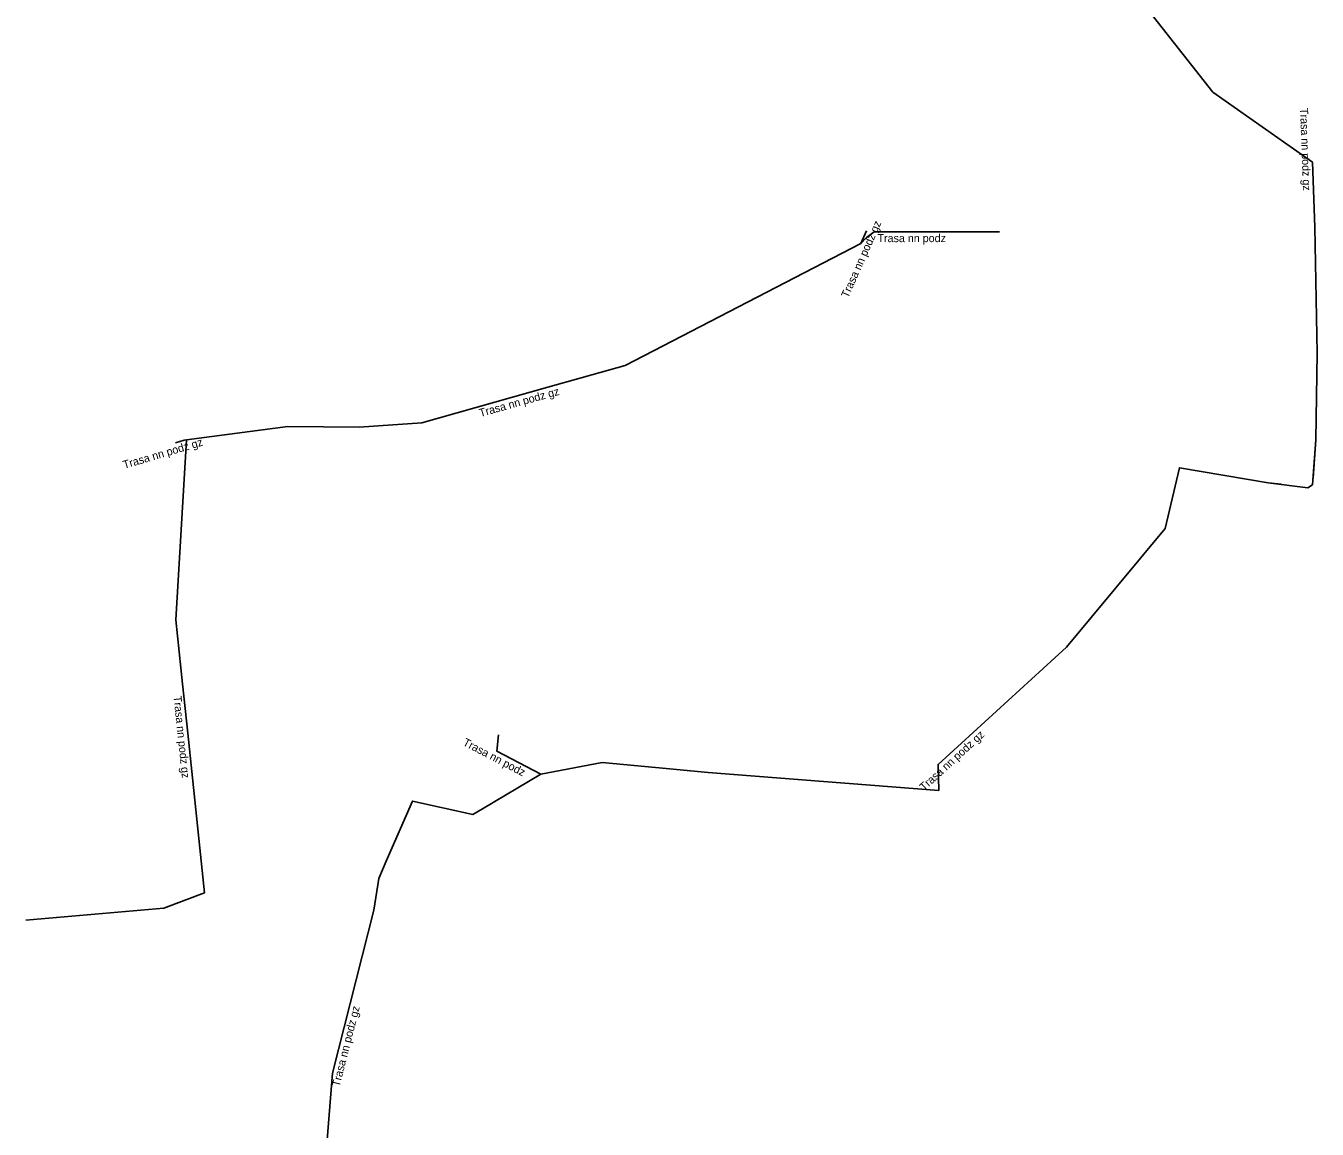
# Model space of a CAD drawing. Extents: x -778200 to -777730, y -1024936 to -1024518.
# Drawn here: x -778006.4 to -777925.8, y -1024799.4 to -1024730.5 of the extents above; entities that cross this region are included whole.
import ezdxf

# ---------------------------------------------------------------- set-up
doc = ezdxf.new("R2010")
doc.units = 0
for name, color, linetype in [('Popiskový text - Ostatní atributy Trasy', 7, 'Continuous'), ('Spojnice NN', 7, 'Continuous'), ('Spojnice VN', 7, 'Continuous')]:
    doc.layers.add(name, color=color, linetype=linetype)

msp = doc.modelspace()

# ---------------------------------------------------------------- linework, layer by layer
at = {"layer": 'Spojnice NN'}
for points in [[(-777926.024, -1024758.713), (-777925.859, -1024756.323), (-777925.772, -1024750.894), (-777925.919, -1024743.043), (-777926.069, -1024738.968), (-777927.663, -1024737.846), (-777932.279, -1024734.598), (-777936.001, -1024729.893), (-777939.603, -1024726.2)], [(-777954.263, -1024744.061), (-777953.915, -1024743.274)], [(-777954.263, -1024744.061), (-777953.928, -1024743.677), (-777953.432, -1024743.322), (-777946.135, -1024743.322), (-777945.617, -1024743.325)], [(-777996.382, -1024756.324), (-777990.058, -1024755.482), (-777985.6, -1024755.517), (-777981.696, -1024755.245), (-777973.822, -1024753.037), (-777968.999, -1024751.684), (-777954.263, -1024744.061)], [(-778006.425, -1024786.306), (-777997.797, -1024785.568), (-777995.266, -1024784.603), (-777996.309, -1024774.633), (-777996.632, -1024771.547), (-777997.051, -1024767.546), (-777996.382, -1024756.324)], [(-777997.067, -1024756.502), (-777996.534, -1024756.344), (-777996.382, -1024756.324)], [(-777974.257, -1024777.202), (-777970.422, -1024776.468), (-777967.09, -1024776.785), (-777963.818, -1024777.096), (-777949.411, -1024778.212), (-777949.445, -1024776.584), (-777945.079, -1024772.597), (-777941.428, -1024769.263), (-777935.268, -1024761.843), (-777934.375, -1024758.06), (-777928.824, -1024758.996), (-777928.014, -1024759.082)], [(-777976.907, -1024774.742), (-777976.998, -1024775.765), (-777974.257, -1024777.202)], [(-777986.982, -1024815.651), (-777988.956, -1024810.759), (-777987.991, -1024804.744), (-777987.946, -1024804.189), (-777987.278, -1024795.861), (-777984.699, -1024785.681), (-777984.386, -1024783.71), (-777983.915, -1024782.626), (-777982.282, -1024778.873), (-777978.5, -1024779.714), (-777977.91, -1024779.356), (-777974.257, -1024777.202)]]:
    msp.add_lwpolyline(points, dxfattribs=at)
at = {"layer": 'Spojnice VN'}
msp.add_lwpolyline([(-777987.946, -1024804.189), (-777987.278, -1024795.861), (-777984.699, -1024785.681), (-777984.386, -1024783.71), (-777983.915, -1024782.626), (-777982.282, -1024778.873), (-777978.5, -1024779.714), (-777977.91, -1024779.356), (-777974.257, -1024777.202), (-777970.422, -1024776.468), (-777967.09, -1024776.785), (-777963.818, -1024777.096), (-777949.411, -1024778.212), (-777949.445, -1024776.584), (-777945.079, -1024772.597), (-777941.428, -1024769.263), (-777935.268, -1024761.843), (-777934.375, -1024758.06), (-777928.824, -1024758.996), (-777926.351, -1024759.31), (-777926.069, -1024759.124), (-777925.859, -1024756.323), (-777925.772, -1024750.894), (-777925.919, -1024743.043), (-777926.069, -1024738.968), (-777927.663, -1024737.846), (-777932.279, -1024734.598), (-777936.001, -1024729.893)], dxfattribs=at)

# ---------------------------------------------------------------- texts
at = {"layer": 'Popiskový text - Ostatní atributy Trasy'}
for s, rotation, p in [('Trasa nn podz gz', 272.1081, (-777926.843, -1024735.602)), ('Trasa nn podz gz', 66.14568, (-777955.069, -1024747.491)), ('Trasa nn podz gz', 15.66438, (-777978.036, -1024754.894)), ('Trasa nn podz gz', 16.51168, (-778000.275, -1024758.131)), ('Trasa nn podz gz', 275.97221, (-777997.203, -1024772.332)), ('Trasa nn podz gz', 42.4021, (-777950.326, -1024778.268)), ('Trasa nn podz', 332.33372, (-777979.172, -1024775.359)), ('Trasa nn podz gz', 75.78379, (-777986.831, -1024796.742))]:
    msp.add_text(s, height=0.5, rotation=rotation, dxfattribs=at).set_placement(p)
msp.add_text('Trasa nn podz', height=0.5, dxfattribs=at).set_placement((-777953.232, -1024743.972))

doc.saveas('drawing.dxf')
